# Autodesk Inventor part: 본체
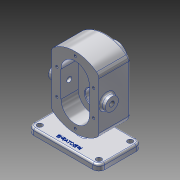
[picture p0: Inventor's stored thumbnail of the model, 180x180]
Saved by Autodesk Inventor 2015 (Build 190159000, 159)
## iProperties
Created: 2019-03
Part Number: 본체
Material: 알루미늄 6061
Document SubType Name: Modeling
Designer: Administrator
Density: 2.7 g/cm^3
Appearance: 알루미늄 - 평지
Mass: 1187.15 g
Surface Area: 719.185 cm^2
Volume: 439.684 cm^3
Author: Administrator
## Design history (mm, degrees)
sketch "스케치1"
  geometry: L1 (-60, 36.5)-(60, 36.5); L2 (60, 36.5)-(60, -36.5); L3 (60, -36.5)-(-60, -36.5); L4 (-60, -36.5)-(-60, 36.5); L5 (-60, 36.5)-(60, -36.5); L6 (60, 36.5)-(-60, -36.5); 1 further point
  constraints: 12 end point, 2 midpoint, 2 parallel, 1 horizontal, 1 perpendicular
  dimensions: "d0" = 120 distance of L2.end L3.end; "d1" = 73 distance of L1.end L2.end
extrude "돌출1" new body sketch "스케치1" distance "d2" = 10; taper "d3" = 0 deg
node "작업 평면1"
sketch "스케치13"
  geometry: L1 (60, 0)-(60, 78); L2 (100, 38)-(100, 118); L3 (20, 38)-(20, 118); A1 r 60 centre (60, 78) between (96, 126) and (24, 126); A2 r 60 centre (60, 78) between (24, 30) and (96, 30); A3 r 10 centre (90, 118) between (100, 118) and (96, 126); A4 r 10 centre (30, 118) between (24, 126) and (20, 118); A5 r 10 centre (30, 38) between (20, 38) and (24, 30); A6 r 10 centre (90, 38) between (96, 30) and (100, 38); 4 further points
  constraints: 16 point on circle, 8 tangent, 6 centre point, 6 end point, 4 point on line, 3 equal radius, 2 parallel, 1 coincident, 1 vertical
  dimensions: "d38" = 78 distance of L1.start L1.end; "d40" = 40 distance between parallel lines of L1 L2; "d41" = 40 distance between parallel lines of L1 L3; "d42" = 60 radius of A1; "d43" = 60 radius of A2; "d44" = 10 radius of A3
extrude "돌출8" join sketch "스케치13" distance "d45" = 53; taper "d46" = 0 deg
sketch "스케치14"
  geometry: L1 (-60, 78)-(-60, 100); L2 (-60, 78)-(-60, 56); L3 (-60, 100)-(-84, 100); L4 (-60, 56)-(-36, 56); L5 (-84, 100)-(-84, 56); L6 (-36, 56)-(-36, 100); A1 r 60 centre (-60, 78) between (-96, 30) and (-24, 30) reference; A2 r 24 centre (-60, 100) between (-36, 100) and (-84, 100); A3 r 24 centre (-60, 56) between (-84, 56) and (-36, 56); 1 further point
  constraints: 12 end point, 4 point on circle, 2 centre point, 2 coincident, 2 point on line, 1 horizontal, 1 parallel, 1 perpendicular, 1 vertical
  dimensions: "d47" = 22 distance of L1.start L1.end; "d48" = 22 distance of L1.start L2.end; "d49" = 24 radius of A2; "d50" = 24 radius of A3
extrude "돌출9" cut sketch "스케치14" distance "d51" = 29; taper "d52" = 0 deg
sketch "스케치15"
  geometry: L1 (-60, 78)-(-60, 100); L2 (-60, 78)-(-60, 56); C1 r 12.5 at (-60, 56); A1 r 60 centre (-60, 78) between (-24, 126) and (-96, 126) reference; 1 further point
  constraints: 4 end point, 1 centre point, 1 coincident, 1 point on line, 1 vertical
  dimensions: "d53" = 22 distance of L1.start L1.end; "d54" = 22 distance of L1.start L2.end; "d55" = 25 diameter of C1
extrude "돌출10" cut sketch "스케치15" distance "d56" = 15; taper "d57" = 0 deg
sketch "스케치16"
  geometry: L1 (-60, 78)-(-60, 100); C1 r 12.5 at (-60, 100); A1 r 60 centre (-60, 78) between (-24, 126) and (-96, 126) reference; 1 further point
  constraints: 2 end point, 1 centre point, 1 coincident, 1 vertical
  dimensions: "d58" = 22 distance of L1.start L1.end; "d59" = 25 diameter of C1
extrude "돌출11" cut sketch "스케치16" distance "d60" = 15; taper "d61" = 0 deg
sketch "스케치17"
  geometry: L1 (60, 78)-(60, 100); C1 r 19 at (60, 100); A1 r 60 centre (60, 78) between (96, 126) and (24, 126) reference; 1 further point
  constraints: 2 end point, 1 centre point, 1 coincident, 1 vertical
  dimensions: "d62" = 22 distance of L1.start L1.end; "d63" = 38 diameter of C1
extrude "돌출12" join sketch "스케치17" distance "d64" = 17; taper "d65" = 0 deg
sketch "스케치18"
  geometry: C1 r 19 at (0, 0) reference; C2 r 14 at (0, 0); 1 further point
  constraints: 1 centre point, 1 coincident
  dimensions: "d66" = 28 diameter of C2
extrude "돌출13" cut sketch "스케치18" distance "d67" = 7.3; taper "d68" = 0 deg
sketch "스케치20"
  geometry: L1 (10, -36.5)-(20, -36.5); L2 (20, -36.5)-(20, 6.5); L3 (20, 6.5)-(10, 6.5); L4 (10, 6.5)-(10, -36.5); 1 further point
  constraints: 8 end point, 2 parallel, 1 horizontal, 1 perpendicular
  dimensions: "d69" = 10 distance of L3.end L2.end; "d70" = 43 distance of L2.end L1.end
extrude "돌출14" join sketch "스케치20" stored distance "d71" = 12; taper "d72" = 0 deg
fillet "모깎기2" dims "d73" = 10
sketch "스케치23"
  geometry: C1 r 4.5 at (-50, -26.5); C2 r 4.5 at (-50, 26.5); C3 r 4.5 at (50, -26.5); C4 r 4.5 at (50, 26.5); A1 r 10 centre (-50, -26.5) between (-60, -26.5) and (-50, -36.5) reference; A2 r 10 centre (-50, 26.5) between (-50, 36.5) and (-60, 26.5) reference; A3 r 10 centre (50, -26.5) between (50, -36.5) and (60, -26.5) reference; A4 r 10 centre (50, 26.5) between (60, 26.5) and (50, 36.5) reference; 1 further point
  constraints: 4 centre point, 4 coincident
  dimensions: "d74" = 9 diameter of C1; "d75" = 9 diameter of C2; "d76" = 9 diameter of C3; "d77" = 9 diameter of C4
extrude "돌출15" cut sketch "스케치23" distance "d78" = 10; taper "d79" = 0 deg
fillet "모깎기3" dims "d80" = 3
fillet "모깎기4" dims "d81" = 3
fillet "모깎기5" dims "d82" = 3
sketch "스케치26"
  geometry: L1 (-60, 100)-(-60, 56); L2 (-60, 100)-(-91, 100); L3 (-60, 56)-(-29, 56); L4 (-91, 100)-(-91, 56); L5 (-29, 56)-(-29, 100); L6 (-60, 100)-(-60, 131); L7 (-60, 56)-(-60, 25); L8 (-60, 56)-(-91, 56); L9 (-60, 100)-(-29, 100); C1 r 12.5 at (-60, 100) reference; C2 r 12.5 at (-60, 56) reference; A1 r 31 centre (-60, 100) between (-29, 100) and (-91, 100); A2 r 31 centre (-60, 56) between (-91, 56) and (-29, 56); 1 further point
  constraints: 18 end point, 6 point on circle, 2 centre point, 2 coincident, 2 parallel, 1 horizontal, 1 tangent, 1 vertical
  dimensions: "d83" = 31 radius of A1; "d84" = 44 distance of L1.start L1.end; "d85" = 31 radius of A2
hole "구멍1" sketch "스케치26" at (-60, 131), (-91, 100), (-29, 100), (-29, 56), (-60, 25), (-91, 56) diameter "d86" = 4.134; stored, may be unused: countersink angle "d90" = 90 deg, drill point angle "d92" = 118 deg; dims "d87" = 10, "d88" = 4, "d89" = 2, "d91" = 12
chamfer "모따기1" distance "d93" = 0.7; stored, may be unused: second distance "d94" = 2, angle "d95" = 30 deg
sketch "스케치31"
  geometry: L1 (0, 62)-(0, 18) reference; L2 (0, 40)-(-14, 40); C1 r 11 at (-14, 40); 1 further point
  constraints: 2 end point, 1 centre point, 1 coincident, 1 horizontal, 1 midpoint
  dimensions: "d106" = 14 distance of L2.start L2.end; "d107" = 22 diameter of C1
extrude "돌출18" join sketch "스케치31" distance "d108" = 8; taper "d109" = 0 deg
sketch "스케치32"
  geometry: L1 (0, 62)-(0, 18) reference; L2 (0, 40)-(14, 40); C1 r 11 at (14, 40) reference; C2 r 11 at (14, 40); 1 further point
  constraints: 2 end point, 1 centre point, 1 coincident, 1 horizontal, 1 midpoint
  dimensions: "d110" = 14 distance of L2.start L2.end (derived); "d111" = 22 diameter of C2
extrude "돌출19" join sketch "스케치32" distance "d112" = 8; taper "d113" = 0 deg
fillet "모깎기6" dims "d114" = 3
sketch "스케치33"
  geometry: C1 r 11 at (0, 0) reference; 2 further points
  constraints: 1 coincident
hole "구멍2" sketch "스케치33" at (0, 0) diameter "d115" = 8.376; stored, may be unused: countersink angle "d119" = 90 deg, drill point angle "d121" = 0 deg; dims "d116" = 20, "d117" = 4, "d118" = 2, "d120" = 14.2
sketch "스케치34"
  geometry: C1 r 11 at (0, 0) reference; 2 further points
  constraints: 1 coincident
hole "구멍3" sketch "스케치34" at (0, 0) diameter "d122" = 8.376; stored, may be unused: countersink angle "d126" = 90 deg, drill point angle "d128" = 0 deg; dims "d123" = 20, "d124" = 4, "d125" = 2, "d127" = 27.3
sketch "스케치35"
  geometry: C1 r 12.5 at (0, 0) reference; C2 r 8.5 at (0, 0); 1 further point
  constraints: 1 centre point, 1 coincident
  dimensions: "d129" = 17 diameter of C2
extrude "돌출20" cut sketch "스케치35" distance "d130" = 19; taper "d131" = 0 deg
chamfer "모따기2" distance "d132" = 1; stored, may be unused: second distance "d133" = 2, angle "d134" = 30 deg
fillet "모깎기7" dims "d135" = 0.5
sketch "스케치37"
  geometry: L1 (-60, -26.5)-(0, -26.5); L2 (-57, -26.5)-(-60, -26.5) reference; 2 further points
  constraints: 2 end point, 1 coincident, 1 collinear, 1 other
  dimensions: "d136" = 60 distance of L1.start L1.end
feature "엠보싱1" sketch "스케치37" dims "d0" = 120, "d1" = 73, "d137" = 0.5, "d138" = 0
fillet "모깎기8" dims "d139" = 3
fillet "모깎기9" dims "d140" = 3
node "솔리드1"
other parameters: "d37" = -53
